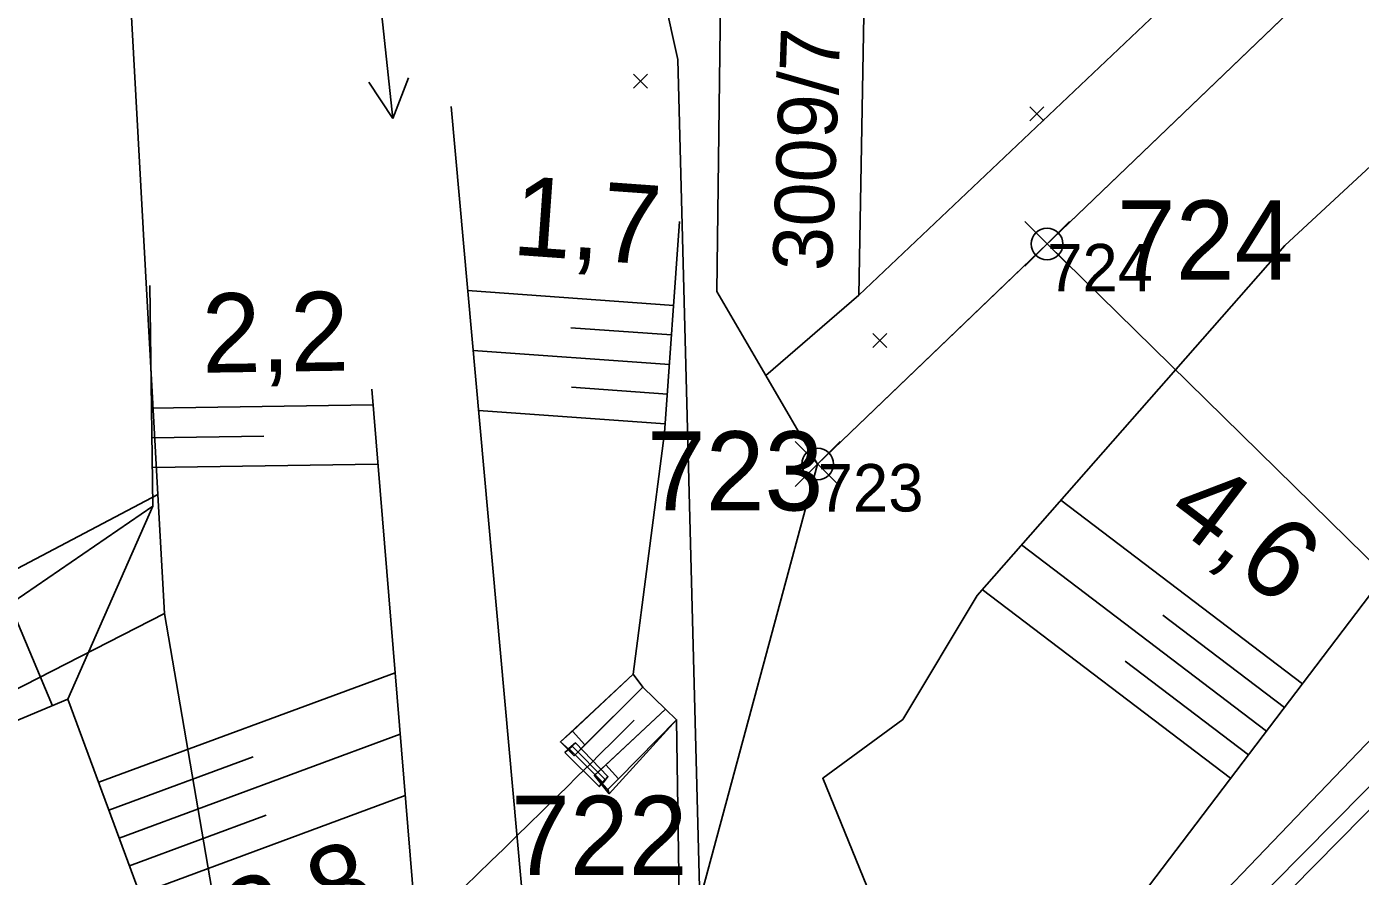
# Model space of a CAD drawing. Extents: x -800194 to -799078, y -1007177 to -1006597.
# Drawn here: x -799442.55 to -799408.83, y -1006874.78 to -1006853.31 of the extents above; entities that cross this region are included whole.
import ezdxf

# ---------------------------------------------------------------- set-up
doc = ezdxf.new("R2010")
doc.units = 0
for name, color, linetype in [('Obvod stavby', 7, 'Continuous'), ('Vrstva 12', 7, 'Continuous'), ('Vrstva 23', 7, 'Continuous'), ('Vrstva 4', 7, 'Continuous'), ('Vrstva 47', 7, 'Continuous'), ('Vrstva 48', 7, 'Continuous'), ('Vrstva 49', 7, 'Continuous'), ('Vrstva 50', 7, 'Continuous'), ('Vrstva 53', 7, 'Continuous'), ('Vrstva 55', 7, 'Continuous'), ('Vrstva 57', 7, 'Continuous'), ('Vrstva 58', 7, 'Continuous'), ('Vrstva 60', 7, 'Continuous')]:
    doc.layers.add(name, color=color, linetype=linetype)

msp = doc.modelspace()

# ---------------------------------------------------------------- linework, layer by layer
at = {"layer": 'Obvod stavby'}
for p, q in [((-799417.313, -1006859.363), (-799416.182, -1006858.232)), ((-799417.313, -1006858.232), (-799416.182, -1006859.363)), ((-799423.116, -1006864.926), (-799421.984, -1006863.794)), ((-799423.116, -1006863.794), (-799421.984, -1006864.926))]:
    msp.add_line(p, q, dxfattribs=at)
msp.add_lwpolyline([(-799559.64, -1006968.48), (-799519.68, -1006952.01), (-799500.87, -1006940.41), (-799496.64, -1006937.8), (-799494.85, -1006936.7), (-799484.52, -1006930.32), (-799457.99, -1006908.8), (-799435, -1006885.17), (-799430.26, -1006880.27), (-799425.53, -1006875.38), (-799422.55, -1006864.36), (-799416.748, -1006858.798), (-799395.763, -1006879.374), (-799413.75, -1006898.23), (-799418.41, -1006902.53), (-799423.07, -1006906.83), (-799433.4, -1006916.39), (-799469.5, -1006946.86), (-799487.22, -1006958.47), (-799495.25, -1006963.74), (-799521.98, -1006977.8), (-799546.71, -1006987.83)], dxfattribs=at)
for centre in [(-799416.748, -1006858.798), (-799422.55, -1006864.36)]:
    msp.add_circle(centre, 0.4, dxfattribs=at)
at = {"layer": 'Vrstva 12'}
for p, q in [((-799428.684, -1006871.709), (-799429.052, -1006871.381)), ((-799427.855, -1006872.588), (-799428.189, -1006872.226))]:
    msp.add_line(p, q, dxfattribs=at)
for points in [[(-799427.212, -1006869.673), (-799429.053, -1006871.381), (-799428.701, -1006871.731), (-799426.968, -1006870.003)], [(-799427.212, -1006869.673), (-799428.749, -1006871.113), (-799428.434, -1006871.455), (-799426.968, -1006870.003), (-799427.212, -1006869.673)], [(-799426.4, -1006870.552), (-799428.191, -1006872.229), (-799427.819, -1006872.693), (-799426.115, -1006870.824)], [(-799426.4, -1006870.552), (-799426.115, -1006870.824), (-799427.583, -1006872.312), (-799427.902, -1006871.962), (-799426.4, -1006870.552)], [(-799428.749, -1006871.113), (-799429.052, -1006871.381), (-799429.053, -1006871.381)], [(-799428.434, -1006871.455), (-799428.684, -1006871.709), (-799428.701, -1006871.731)], [(-799427.902, -1006871.962), (-799428.189, -1006872.226), (-799428.191, -1006872.229)], [(-799427.819, -1006872.693), (-799427.855, -1006872.588), (-799427.583, -1006872.312)]]:
    msp.add_lwpolyline(points, dxfattribs=at)
at = {"layer": 'Vrstva 23'}
for p, q in [((-799428.071, -1006872.51), (-799428.937, -1006871.65)), ((-799428.839, -1006871.551), (-799427.97, -1006872.42)), ((-799427.924, -1006872.333), (-799428.753, -1006871.491)), ((-799428.675, -1006871.409), (-799427.852, -1006872.259))]:
    msp.add_line(p, q, dxfattribs=at)
for points in [[(-799428.937, -1006871.65), (-799428.839, -1006871.551), (-799428.675, -1006871.409), (-799428.753, -1006871.491), (-799428.937, -1006871.65)], [(-799427.924, -1006872.333), (-799427.852, -1006872.259), (-799427.97, -1006872.42), (-799428.071, -1006872.51), (-799427.924, -1006872.333)]]:
    msp.add_lwpolyline(points, dxfattribs=at)
at = {"layer": 'Vrstva 4'}
for points in [[(-799415.349, -1006878.386), (-799401.641, -1006864.104), (-799387.486, -1006849.959), (-799372.535, -1006834.618), (-799359.471, -1006821.017), (-799348.425, -1006810.321), (-799332.246, -1006792.656), (-799316.193, -1006777.023)], [(-799414.896, -1006878.87), (-799401.02, -1006864.85), (-799386.827, -1006850.567), (-799372.152, -1006835.069), (-799358.827, -1006821.464), (-799347.624, -1006811), (-799330.977, -1006793.164), (-799315.559, -1006777.544)], [(-799510.394, -1006958.536), (-799498.027, -1006951.328), (-799477.988, -1006937.435), (-799460.33, -1006923.117), (-799451.862, -1006915.581), (-799443.604, -1006907.9), (-799435.444, -1006900.067), (-799428.64, -1006893.299), (-799422.817, -1006887.511), (-799415.998, -1006880.595), (-799408.158, -1006872.652), (-799401.02, -1006864.85)]]:
    msp.add_lwpolyline(points, dxfattribs=at)
at = {"layer": 'Vrstva 47'}
msp.add_ellipse((-799432.733, -1006875.845), major_axis=(8.482, 8.158), ratio=0.02521, start_param=4.117511, end_param=5.400082, dxfattribs=at)
at = {"layer": 'Vrstva 48'}
for p, q in [((-799426.189, -1006860.351), (-799431.398, -1006859.979)), ((-799426.243, -1006861.099), (-799428.786, -1006860.917)), ((-799426.296, -1006861.847), (-799431.261, -1006861.492)), ((-799426.349, -1006862.595), (-799428.771, -1006862.422)), ((-799439.39, -1006862.948), (-799433.792, -1006862.864)), ((-799426.403, -1006863.343), (-799431.124, -1006863.006)), ((-799439.379, -1006863.698), (-799436.554, -1006863.656)), ((-799439.368, -1006864.447), (-799433.668, -1006864.363)), ((-799410.295, -1006869.914), (-799416.403, -1006865.276)), ((-799411.202, -1006871.109), (-799417.396, -1006866.406)), ((-799412.109, -1006872.303), (-799418.389, -1006867.535)), ((-799441.897, -1006870.468), (-799442.971, -1006867.903)), ((-799410.749, -1006870.511), (-799413.824, -1006868.176)), ((-799440.726, -1006872.404), (-799433.232, -1006869.633)), ((-799411.656, -1006871.706), (-799414.774, -1006869.338)), ((-799440.206, -1006873.811), (-799433.104, -1006871.185)), ((-799440.466, -1006873.108), (-799436.817, -1006871.758)), ((-799439.685, -1006875.218), (-799432.976, -1006872.737)), ((-799439.946, -1006874.515), (-799436.493, -1006873.238))]:
    msp.add_line(p, q, dxfattribs=at)
at = {"layer": 'Vrstva 49'}
for p, q in [((-799427.202, -1006854.504), (-799426.848, -1006854.858)), ((-799427.202, -1006854.858), (-799426.848, -1006854.504)), ((-799417.188, -1006855.332), (-799416.834, -1006855.686)), ((-799417.188, -1006855.686), (-799416.834, -1006855.332)), ((-799421.151, -1006861.062), (-799420.797, -1006861.416)), ((-799421.151, -1006861.416), (-799420.797, -1006861.062))]:
    msp.add_line(p, q, dxfattribs=at)
for points in [[(-799327.095, -1006776.084), (-799339.676, -1006790.63), (-799358.716, -1006807.195), (-799375.729, -1006824.95), (-799393.254, -1006842.64), (-799410.738, -1006858.834), (-799418.516, -1006867.679), (-799420.397, -1006870.813)], [(-799416.02, -1006877.454), (-799404.211, -1006861.901), (-799389.752, -1006848.65), (-799373.943, -1006833.474), (-799360.851, -1006819.663), (-799350.223, -1006808.887), (-799332.885, -1006792.133), (-799317.349, -1006776.174)], [(-799410.227, -1006925.149), (-799412.491, -1006911.033), (-799419.106, -1006898.668), (-799423.582, -1006889.778), (-799429.735, -1006878.378), (-799431.818, -1006855.328)], [(-799426.038, -1006858.234), (-799426.419, -1006863.568), (-799427.212, -1006869.673), (-799426.968, -1006870.003), (-799426.4, -1006870.552), (-799426.115, -1006870.824), (-799426.018, -1006877.519), (-799424.103, -1006883.903), (-799422.705, -1006885.358), (-799423.751, -1006886.402), (-799420.096, -1006889.979), (-799419.086, -1006888.964), (-799412.022, -1006900.113), (-799405.487, -1006924.286)], [(-799427.694, -1006890.471), (-799427.892, -1006890.566), (-799432.944, -1006889.197), (-799436.923, -1006881.42), (-799437.363, -1006881.152), (-799437.876, -1006880.464), (-799438.146, -1006880.193), (-799438.528, -1006878.348), (-799441.503, -1006870.303), (-799439.353, -1006865.427), (-799439.436, -1006859.851)], [(-799433.824, -1006862.471), (-799432.369, -1006880.085), (-799427.694, -1006890.471)], [(-799461.444, -1006891.51), (-799455.403, -1006884.501), (-799445.66, -1006878.142), (-799444.968, -1006869.269), (-799439.353, -1006865.427)], [(-799461.444, -1006891.51), (-799453.63, -1006885.576), (-799442.951, -1006879.899), (-799443.72, -1006871.232), (-799441.503, -1006870.303)], [(-799418.695, -1006881.438), (-799422.419, -1006872.299), (-799420.397, -1006870.813)]]:
    msp.add_lwpolyline(points, dxfattribs=at)
at = {"layer": 'Vrstva 50'}
for points in [[(-799431.818, -1006855.328), (-799429.735, -1006878.378), (-799423.582, -1006889.778), (-799419.106, -1006898.668), (-799412.491, -1006911.033), (-799410.227, -1006925.149)], [(-799433.824, -1006862.471), (-799432.369, -1006880.085), (-799427.694, -1006890.471), (-799424.101, -1006893.992), (-799424.223, -1006894.144), (-799421.688, -1006901.262), (-799414.969, -1006911.36), (-799413.387, -1006925.296)]]:
    msp.add_lwpolyline(points, dxfattribs=at)
at = {"layer": 'Vrstva 53'}
msp.add_lwpolyline([(-799559.64, -1006968.48), (-799519.68, -1006952.01), (-799500.87, -1006940.41), (-799496.64, -1006937.8), (-799494.85, -1006936.7), (-799484.519, -1006930.319), (-799457.99, -1006908.8), (-799435, -1006885.17), (-799430.26, -1006880.27), (-799425.53, -1006875.38), (-799422.55, -1006864.36), (-799390.88, -1006834), (-799358.35, -1006806.65), (-799352.29, -1006801.56), (-799330.91, -1006783.58), (-799314.235, -1006766.649)], dxfattribs=at)
at = {"layer": 'Vrstva 55'}
for p, q in [((-799390.88, -1006834), (-799422.55, -1006864.36)), ((-799421.3, -1006848.64), (-799421.51, -1006860.09)), ((-799423.86, -1006862.12), (-799421.51, -1006860.09)), ((-799422.55, -1006864.36), (-799423.86, -1006862.12)), ((-799425.53, -1006875.38), (-799422.55, -1006864.36)), ((-799439.23, -1006865.13), (-799439.06, -1006868.14))]:
    msp.add_line(p, q, dxfattribs=at)
for points in [[(-799435.887, -1006766.649), (-799434.45, -1006772.74), (-799433.92, -1006782.05), (-799434.12, -1006788.57), (-799439.66, -1006821.53), (-799440.71, -1006838.23), (-799439.23, -1006865.13)], [(-799422.547, -1006766.649), (-799420.88, -1006776.85), (-799422, -1006788.79), (-799422.77, -1006803.25), (-799426.4, -1006820.84), (-799428.26, -1006838.83), (-799427.88, -1006846.03), (-799426.08, -1006854.14), (-799425.53, -1006875.38)], [(-799421.51, -1006860.09), (-799407.9, -1006847.2), (-799393.66, -1006833.58), (-799374.69, -1006803.75)], [(-799423.86, -1006862.12), (-799425.1, -1006860), (-799425, -1006852)], [(-799498.58, -1006896.8), (-799468.62, -1006880.61), (-799439.23, -1006865.13)], [(-799439.06, -1006868.14), (-799466.75, -1006882.3), (-799482.8, -1006890.48), (-799499.57, -1006898.99), (-799506.49, -1006901.85)], [(-799435, -1006885.17), (-799437.37, -1006878.01), (-799439.06, -1006868.14)]]:
    msp.add_lwpolyline(points, dxfattribs=at)
at = {"layer": 'Vrstva 58'}
for p, q in [((-799433.933, -1006849.66), (-799433.288, -1006855.625)), ((-799433.288, -1006855.625), (-799433.893, -1006854.707)), ((-799433.288, -1006855.625), (-799432.895, -1006854.6))]:
    msp.add_line(p, q, dxfattribs=at)
at = {"layer": 'Vrstva 60'}
for p, q in [((-799416.748, -1006858.798), (-799416.748, -1006858.798)), ((-799422.55, -1006864.36), (-799422.55, -1006864.36))]:
    msp.add_line(p, q, dxfattribs=at)

# ---------------------------------------------------------------- texts
at = {"layer": 'Obvod stavby'}
for s, p in [('724', (-799414.985, -1006859.7)), ('723', (-799426.867, -1006865.533)), ('722', (-799430.302, -1006874.744))]:
    msp.add_text(s, height=2, rotation=360, dxfattribs=at).set_placement(p)
at = {"layer": 'Vrstva 48'}
for s, rotation, p in [('1,7', 355.9144, (-799430.298, -1006859.067)), ('2,2', 0.8528, (-799438.104, -1006862.054)), ('4,6', 322.7915, (-799413.815, -1006865.73)), ('2,8', 20.2941, (-799437.062, -1006876.949))]:
    msp.add_text(s, height=2, rotation=rotation, dxfattribs=at).set_placement(p)
at = {"layer": 'Vrstva 57'}
msp.add_text('3009/7', height=1.5, rotation=88, dxfattribs=at).set_placement((-799422.19, -1006859.499))
at = {"layer": 'Vrstva 60'}
for s, p in [('724', (-799416.748, -1006859.998)), ('723', (-799422.55, -1006865.56))]:
    msp.add_text(s, height=1.2, dxfattribs=at).set_placement(p)

doc.saveas('drawing.dxf')
